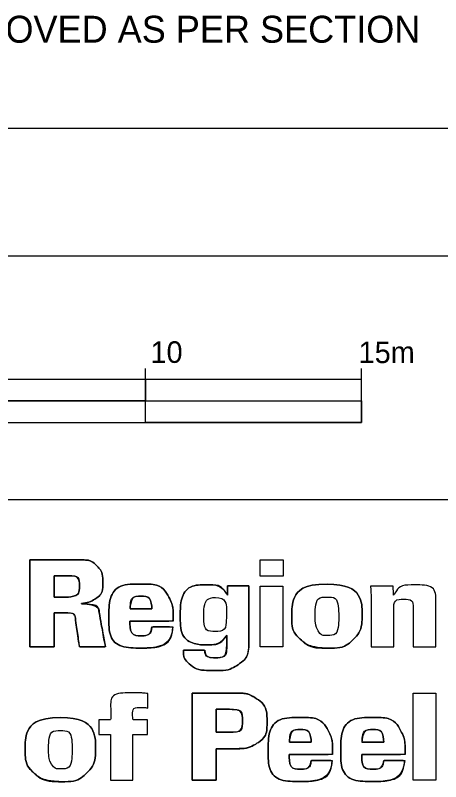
# Model space of a CAD drawing. Extents: x 612883 to 613093, y 4825734 to 4825879.
# Drawn here: x 613071.55 to 613081.4, y 4825752.4 to 4825770.16 of the extents above; entities that cross this region are included whole.
import ezdxf

# ---------------------------------------------------------------- set-up
doc = ezdxf.new("R2010")
doc.units = 0
for name, color, linetype in [('G-ANNO-BAR', 7, 'Continuous'), ('G-ANNO-TEXT', 7, 'Continuous'), ('G-TTLB-LOGO', 7, 'Continuous'), ('G-TTLB-OTLN', 7, 'Continuous')]:
    doc.layers.add(name, color=color, linetype=linetype)

msp = doc.modelspace()

# ---------------------------------------------------------------- linework, layer by layer
at = {"layer": 'G-ANNO-BAR'}
for p, q in [((613074.564, 4825760.723), (613074.564, 4825761.973)), ((613079.564, 4825760.723), (613079.564, 4825761.973)), ((613059.564, 4825761.723), (613079.564, 4825761.723)), ((613059.564, 4825761.223), (613079.564, 4825761.223)), ((613059.564, 4825760.723), (613079.564, 4825760.723))]:
    msp.add_line(p, q, dxfattribs=at)
for points in [[(613069.564, 4825761.723), (613074.564, 4825761.723), (613074.564, 4825761.223), (613069.564, 4825761.223)], [(613074.564, 4825761.223), (613079.564, 4825761.223), (613079.564, 4825760.723), (613074.564, 4825760.723)]]:
    msp.add_lwpolyline(points, close=True, dxfattribs=at)
at = {"layer": 'G-TTLB-LOGO'}
for p, q in [((613077.215, 4825757.537), (613077.752, 4825757.537)), ((613077.215, 4825757.162), (613077.215, 4825757.537)), ((613077.752, 4825757.537), (613077.752, 4825757.162)), ((613077.752, 4825757.162), (613077.215, 4825757.162)), ((613077.22, 4825756.927), (613077.746, 4825756.927)), ((613077.22, 4825755.523), (613077.22, 4825756.927)), ((613077.746, 4825756.927), (613077.746, 4825755.523)), ((613073.082, 4825756.527), (613073.082, 4825756.516)), ((613074.204, 4825756.404), (613074.71, 4825756.404)), ((613075.205, 4825756.119), (613074.198, 4825756.119)), ((613074.707, 4825755.982), (613075.197, 4825755.982)), ((613076.443, 4825755.61), (613076.443, 4825755.795)), ((613073.636, 4825755.523), (613073.029, 4825755.523)), ((613075.439, 4825755.448), (613075.934, 4825755.448)), ((613077.746, 4825755.523), (613077.22, 4825755.523)), ((613080.763, 4825754.449), (613081.289, 4825754.449)), ((613080.763, 4825752.43), (613080.763, 4825754.449)), ((613081.289, 4825754.449), (613081.289, 4825752.43)), ((613077.896, 4825753.311), (613078.402, 4825753.311)), ((613079.577, 4825753.311), (613080.083, 4825753.311)), ((613078.897, 4825753.025), (613077.89, 4825753.025)), ((613080.578, 4825753.025), (613079.571, 4825753.025)), ((613078.399, 4825752.888), (613078.888, 4825752.888)), ((613080.08, 4825752.888), (613080.569, 4825752.888)), ((613081.289, 4825752.43), (613080.763, 4825752.43))]:
    msp.add_line(p, q, dxfattribs=at)
for points in [[(613072.677, 4825756.312), (613072.442, 4825756.312), (613072.442, 4825755.523), (613071.88, 4825755.523), (613071.88, 4825757.542), (613072.814, 4825757.542)], [(613077.215, 4825757.537), (613077.752, 4825757.537), (613077.752, 4825757.162), (613077.215, 4825757.162), (613077.215, 4825757.537)], [(613072.652, 4825757.171), (613072.442, 4825757.171), (613072.442, 4825756.676), (613072.652, 4825756.676)], [(613076.46, 4825756.723), (613076.46, 4825756.936), (613076.955, 4825756.936), (613076.955, 4825755.627)], [(613077.22, 4825756.927), (613077.746, 4825756.927), (613077.746, 4825755.523), (613077.22, 4825755.523), (613077.22, 4825756.927)], [(613076.565, 4825753.16), (613076.201, 4825753.157), (613076.201, 4825752.43), (613075.639, 4825752.43), (613075.639, 4825754.449), (613076.567, 4825754.449)], [(613080.763, 4825754.449), (613081.289, 4825754.449), (613081.289, 4825752.43), (613080.763, 4825752.43), (613080.763, 4825754.449)], [(613076.447, 4825754.074), (613076.201, 4825754.074), (613076.201, 4825753.543), (613076.45, 4825753.543)]]:
    msp.add_lwpolyline(points, dxfattribs=at)
for points in [[(613071.88, 4825757.542), (613071.88, 4825757.542), (613072.814, 4825757.542), (613072.814, 4825757.542), (613073.177, 4825757.542), (613073.314, 4825757.52), (613073.435, 4825757.397), (613073.496, 4825757.336), (613073.574, 4825757.224), (613073.574, 4825757.006), (613073.574, 4825756.785), (613073.485, 4825756.69), (613073.39, 4825756.631), (613073.261, 4825756.55), (613073.138, 4825756.536), (613073.082, 4825756.527), (613073.082, 4825756.527), (613073.082, 4825756.516), (613073.082, 4825756.516), (613073.474, 4825756.505), (613073.482, 4825756.333), (613073.541, 4825756.021), (613073.567, 4825755.885), (613073.612, 4825755.621), (613073.636, 4825755.523), (613073.636, 4825755.523), (613073.029, 4825755.523), (613073.029, 4825755.523), (613073.019, 4825755.595), (613072.991, 4825755.805), (613072.967, 4825755.96), (613072.931, 4825756.202), (613072.928, 4825756.312), (613072.677, 4825756.312), (613072.677, 4825756.312), (613072.442, 4825756.312), (613072.442, 4825756.312), (613072.442, 4825756.312), (613072.442, 4825755.523), (613072.442, 4825755.523), (613072.442, 4825755.523), (613071.88, 4825755.523), (613071.88, 4825755.523), (613071.88, 4825755.523), (613071.88, 4825757.542), (613071.88, 4825757.542)], [(613072.814, 4825757.542), (613073.177, 4825757.542), (613073.314, 4825757.52), (613073.435, 4825757.397), (613073.496, 4825757.336), (613073.574, 4825757.224), (613073.574, 4825757.006), (613073.574, 4825756.785), (613073.485, 4825756.69), (613073.39, 4825756.631), (613073.261, 4825756.55), (613073.138, 4825756.536), (613073.082, 4825756.527)], [(613072.442, 4825756.676), (613072.442, 4825756.676), (613072.652, 4825756.676), (613072.652, 4825756.676), (613072.775, 4825756.676), (613072.836, 4825756.676), (613072.884, 4825756.692), (613073.007, 4825756.732), (613073.032, 4825756.857), (613073.032, 4825756.922), (613073.032, 4825757.171), (613072.814, 4825757.171), (613072.652, 4825757.171), (613072.652, 4825757.171), (613072.442, 4825757.171), (613072.442, 4825757.171), (613072.442, 4825757.171), (613072.442, 4825756.676), (613072.442, 4825756.676)], [(613072.652, 4825756.676), (613072.775, 4825756.676), (613072.836, 4825756.676), (613072.884, 4825756.692), (613073.007, 4825756.732), (613073.032, 4825756.857), (613073.032, 4825756.922), (613073.032, 4825757.171), (613072.814, 4825757.171), (613072.652, 4825757.171)], [(613074.198, 4825756.119), (613074.198, 4825756.044), (613074.198, 4825755.778), (613074.467, 4825755.778), (613074.607, 4825755.778), (613074.693, 4825755.851), (613074.707, 4825755.982), (613074.707, 4825755.982), (613075.197, 4825755.982), (613075.197, 4825755.982), (613075.158, 4825755.63), (613074.828, 4825755.493), (613074.464, 4825755.493), (613073.975, 4825755.493), (613073.712, 4825755.739), (613073.712, 4825756.203), (613073.712, 4825756.673), (613073.941, 4825756.978), (613074.458, 4825756.978), (613074.85, 4825756.978), (613075.032, 4825756.818), (613075.127, 4825756.62), (613075.188, 4825756.499), (613075.205, 4825756.365), (613075.205, 4825756.119), (613075.205, 4825756.119), (613074.198, 4825756.119), (613074.198, 4825756.119)], [(613075.197, 4825755.982), (613075.158, 4825755.63), (613074.828, 4825755.493), (613074.464, 4825755.493), (613073.975, 4825755.493), (613073.712, 4825755.739), (613073.712, 4825756.203), (613073.712, 4825756.673), (613073.941, 4825756.978), (613074.458, 4825756.978), (613074.85, 4825756.978), (613075.032, 4825756.818), (613075.127, 4825756.62), (613075.188, 4825756.499), (613075.205, 4825756.365), (613075.205, 4825756.119)], [(613076.955, 4825756.936), (613076.955, 4825756.936), (613076.955, 4825755.627), (613076.955, 4825755.627), (613076.955, 4825755.459), (613076.921, 4825755.261), (613076.731, 4825755.126), (613076.611, 4825755.04), (613076.44, 4825754.97), (613076.153, 4825754.97), (613075.993, 4825754.97), (613075.727, 4825754.992), (613075.568, 4825755.135), (613075.445, 4825755.244), (613075.442, 4825755.375), (613075.439, 4825755.448), (613075.439, 4825755.448), (613075.934, 4825755.448), (613075.934, 4825755.448), (613075.937, 4825755.342), (613076.013, 4825755.269), (613076.164, 4825755.269), (613076.427, 4825755.269), (613076.443, 4825755.459), (613076.443, 4825755.61), (613076.443, 4825755.61), (613076.443, 4825755.795), (613076.443, 4825755.795), (613076.301, 4825755.582), (613076.071, 4825755.568), (613075.99, 4825755.568), (613075.694, 4825755.568), (613075.367, 4825755.753), (613075.367, 4825756.265), (613075.367, 4825756.645), (613075.568, 4825756.961), (613075.996, 4825756.961), (613076.267, 4825756.961), (613076.39, 4825756.835), (613076.46, 4825756.723), (613076.46, 4825756.723), (613076.46, 4825756.936), (613076.46, 4825756.936), (613076.46, 4825756.936), (613076.955, 4825756.936), (613076.955, 4825756.936)], [(613076.443, 4825755.795), (613076.301, 4825755.582), (613076.071, 4825755.568), (613075.99, 4825755.568), (613075.694, 4825755.568), (613075.367, 4825755.753), (613075.367, 4825756.265), (613075.367, 4825756.645), (613075.568, 4825756.961), (613075.996, 4825756.961), (613076.267, 4825756.961), (613076.39, 4825756.835), (613076.46, 4825756.723)], [(613078.77, 4825756.975), (613079.226, 4825756.975), (613079.581, 4825756.746), (613079.581, 4825756.248), (613079.581, 4825756.044), (613079.522, 4825755.837), (613079.377, 4825755.691), (613079.259, 4825755.577), (613079.086, 4825755.49), (613078.798, 4825755.49), (613078.487, 4825755.49), (613078.286, 4825755.565), (613078.149, 4825755.697), (613077.987, 4825755.851), (613077.948, 4825756.06), (613077.948, 4825756.231), (613077.948, 4825756.662), (613078.213, 4825756.975), (613078.77, 4825756.975)], [(613078.62, 4825755.499), (613078.407, 4825755.523), (613078.258, 4825755.592), (613078.149, 4825755.697), (613077.987, 4825755.851), (613077.948, 4825756.06), (613077.948, 4825756.231), (613077.948, 4825756.662), (613078.213, 4825756.975), (613078.77, 4825756.975)], [(613078.77, 4825756.975), (613079.226, 4825756.975), (613079.581, 4825756.746), (613079.581, 4825756.248), (613079.581, 4825756.044), (613079.522, 4825755.837), (613079.377, 4825755.691), (613079.259, 4825755.577), (613079.086, 4825755.49), (613078.798, 4825755.49), (613078.734, 4825755.49), (613078.675, 4825755.493), (613078.62, 4825755.499)], [(613079.79, 4825756.628), (613079.79, 4825756.628), (613079.776, 4825756.927), (613079.776, 4825756.927), (613079.776, 4825756.927), (613080.301, 4825756.927), (613080.301, 4825756.927), (613080.301, 4825756.927), (613080.307, 4825756.712), (613080.307, 4825756.712), (613080.371, 4825756.818), (613080.483, 4825756.958), (613080.774, 4825756.958), (613081.289, 4825756.958), (613081.289, 4825756.567), (613081.289, 4825756.374), (613081.289, 4825756.374), (613081.289, 4825755.523), (613081.289, 4825755.523), (613081.289, 4825755.523), (613080.763, 4825755.523), (613080.763, 4825755.523), (613080.763, 4825755.523), (613080.763, 4825756.329), (613080.763, 4825756.329), (613080.763, 4825756.427), (613080.763, 4825756.625), (613080.548, 4825756.625), (613080.313, 4825756.625), (613080.313, 4825756.379), (613080.313, 4825756.329), (613080.313, 4825756.329), (613080.313, 4825755.523), (613080.313, 4825755.523), (613080.313, 4825755.523), (613079.79, 4825755.523), (613079.79, 4825755.523), (613079.79, 4825755.523), (613079.79, 4825756.628), (613079.79, 4825756.628)], [(613079.79, 4825756.628), (613079.79, 4825756.628), (613079.776, 4825756.927), (613079.776, 4825756.927), (613079.776, 4825756.927), (613080.301, 4825756.927), (613080.301, 4825756.927), (613080.301, 4825756.927), (613080.307, 4825756.712), (613080.307, 4825756.712), (613080.371, 4825756.818), (613080.483, 4825756.958), (613080.774, 4825756.958), (613081.289, 4825756.958), (613081.289, 4825756.567), (613081.289, 4825756.374), (613081.289, 4825756.374), (613081.289, 4825755.523), (613081.289, 4825755.523), (613081.289, 4825755.523), (613080.763, 4825755.523), (613080.763, 4825755.523), (613080.763, 4825755.523), (613080.763, 4825756.329), (613080.763, 4825756.329), (613080.763, 4825756.427), (613080.763, 4825756.625), (613080.548, 4825756.625), (613080.313, 4825756.625), (613080.313, 4825756.379), (613080.313, 4825756.329), (613080.313, 4825756.329), (613080.313, 4825755.523), (613080.313, 4825755.523), (613080.313, 4825755.523), (613079.79, 4825755.523), (613079.79, 4825755.523), (613079.79, 4825755.523), (613079.79, 4825756.628), (613079.79, 4825756.628)], [(613074.71, 4825756.404), (613074.705, 4825756.485), (613074.688, 4825756.698), (613074.458, 4825756.698), (613074.229, 4825756.698), (613074.21, 4825756.471), (613074.204, 4825756.404), (613074.204, 4825756.404), (613074.71, 4825756.404), (613074.71, 4825756.404)], [(613074.71, 4825756.404), (613074.705, 4825756.485), (613074.688, 4825756.698), (613074.458, 4825756.698), (613074.229, 4825756.698), (613074.21, 4825756.471), (613074.204, 4825756.404)], [(613076.18, 4825756.667), (613076.004, 4825756.667), (613075.909, 4825756.505), (613075.909, 4825756.27), (613075.909, 4825756.122), (613075.943, 4825755.879), (613076.175, 4825755.879), (613076.427, 4825755.879), (613076.435, 4825756.175), (613076.435, 4825756.276), (613076.435, 4825756.348), (613076.435, 4825756.667), (613076.18, 4825756.667)], [(613076.18, 4825756.667), (613076.004, 4825756.667), (613075.909, 4825756.505), (613075.909, 4825756.27), (613075.909, 4825756.122), (613075.943, 4825755.879), (613076.175, 4825755.879), (613076.427, 4825755.879), (613076.435, 4825756.175), (613076.435, 4825756.276), (613076.435, 4825756.348), (613076.435, 4825756.667), (613076.18, 4825756.667)], [(613078.56, 4825755.895), (613078.622, 4825755.789), (613078.717, 4825755.784), (613078.764, 4825755.784), (613078.994, 4825755.784), (613079.038, 4825756.032), (613079.038, 4825756.228), (613079.038, 4825756.471), (613078.98, 4825756.676), (613078.77, 4825756.676), (613078.538, 4825756.676), (613078.493, 4825756.438), (613078.493, 4825756.228), (613078.493, 4825756.136), (613078.501, 4825755.999), (613078.56, 4825755.895)], [(613078.56, 4825755.895), (613078.622, 4825755.789), (613078.717, 4825755.784), (613078.764, 4825755.784), (613078.994, 4825755.784), (613079.038, 4825756.032), (613079.038, 4825756.228), (613079.038, 4825756.471), (613078.98, 4825756.676), (613078.77, 4825756.676), (613078.538, 4825756.676), (613078.493, 4825756.438), (613078.493, 4825756.228), (613078.493, 4825756.136), (613078.501, 4825755.999), (613078.56, 4825755.895)], [(613073.082, 4825756.516), (613073.474, 4825756.505), (613073.482, 4825756.333), (613073.541, 4825756.021), (613073.567, 4825755.885), (613073.612, 4825755.621), (613073.636, 4825755.523)], [(613073.029, 4825755.523), (613073.019, 4825755.595), (613072.991, 4825755.805), (613072.967, 4825755.96), (613072.931, 4825756.202), (613072.928, 4825756.312), (613072.677, 4825756.312)], [(613074.198, 4825756.119), (613074.198, 4825756.044), (613074.198, 4825755.778), (613074.467, 4825755.778), (613074.607, 4825755.778), (613074.693, 4825755.851), (613074.707, 4825755.982)], [(613076.955, 4825755.627), (613076.955, 4825755.459), (613076.921, 4825755.261), (613076.731, 4825755.126), (613076.611, 4825755.04), (613076.44, 4825754.97), (613076.153, 4825754.97), (613075.993, 4825754.97), (613075.727, 4825754.992), (613075.568, 4825755.135), (613075.445, 4825755.244), (613075.442, 4825755.375), (613075.439, 4825755.448)], [(613075.934, 4825755.448), (613075.937, 4825755.342), (613076.013, 4825755.269), (613076.164, 4825755.269), (613076.427, 4825755.269), (613076.443, 4825755.459), (613076.443, 4825755.61)], [(613074.618, 4825754.102), (613074.596, 4825754.108), (613074.543, 4825754.119), (613074.473, 4825754.119), (613074.257, 4825754.119), (613074.263, 4825753.945), (613074.266, 4825753.828), (613074.266, 4825753.828), (613074.604, 4825753.828), (613074.604, 4825753.828), (613074.604, 4825753.828), (613074.604, 4825753.487), (613074.604, 4825753.487), (613074.604, 4825753.487), (613074.266, 4825753.487), (613074.266, 4825753.487), (613074.266, 4825753.487), (613074.266, 4825752.43), (613074.266, 4825752.43), (613074.266, 4825752.43), (613073.751, 4825752.43), (613073.751, 4825752.43), (613073.751, 4825752.43), (613073.751, 4825753.487), (613073.751, 4825753.487), (613073.751, 4825753.487), (613073.48, 4825753.487), (613073.48, 4825753.487), (613073.48, 4825753.487), (613073.48, 4825753.828), (613073.48, 4825753.828), (613073.48, 4825753.828), (613073.76, 4825753.828), (613073.76, 4825753.828), (613073.751, 4825754.164), (613073.757, 4825754.457), (613074.308, 4825754.457), (613074.451, 4825754.457), (613074.559, 4825754.446), (613074.618, 4825754.44), (613074.618, 4825754.44), (613074.618, 4825754.102), (613074.618, 4825754.102)], [(613074.618, 4825754.102), (613074.596, 4825754.108), (613074.543, 4825754.119), (613074.473, 4825754.119), (613074.257, 4825754.119), (613074.263, 4825753.945), (613074.266, 4825753.828), (613074.266, 4825753.828), (613074.604, 4825753.828), (613074.604, 4825753.828), (613074.604, 4825753.828), (613074.604, 4825753.487), (613074.604, 4825753.487), (613074.604, 4825753.487), (613074.266, 4825753.487), (613074.266, 4825753.487), (613074.266, 4825753.487), (613074.266, 4825752.43), (613074.266, 4825752.43), (613074.266, 4825752.43), (613073.751, 4825752.43), (613073.751, 4825752.43), (613073.751, 4825752.43), (613073.751, 4825753.487), (613073.751, 4825753.487), (613073.751, 4825753.487), (613073.48, 4825753.487), (613073.48, 4825753.487), (613073.48, 4825753.487), (613073.48, 4825753.828), (613073.48, 4825753.828), (613073.48, 4825753.828), (613073.76, 4825753.828), (613073.76, 4825753.828), (613073.751, 4825754.164), (613073.757, 4825754.457), (613074.308, 4825754.457), (613074.451, 4825754.457), (613074.559, 4825754.446), (613074.618, 4825754.44), (613074.618, 4825754.44), (613074.618, 4825754.102), (613074.618, 4825754.102)], [(613075.639, 4825754.449), (613075.639, 4825754.449), (613076.567, 4825754.449), (613076.567, 4825754.449), (613076.724, 4825754.449), (613076.928, 4825754.449), (613077.093, 4825754.345), (613077.264, 4825754.242), (613077.378, 4825754.06), (613077.378, 4825753.797), (613077.378, 4825753.442), (613077.152, 4825753.288), (613077.074, 4825753.246), (613076.917, 4825753.16), (613076.674, 4825753.16), (613076.565, 4825753.16), (613076.565, 4825753.16), (613076.201, 4825753.157), (613076.201, 4825753.157), (613076.201, 4825753.157), (613076.201, 4825752.43), (613076.201, 4825752.43), (613076.201, 4825752.43), (613075.639, 4825752.43), (613075.639, 4825752.43), (613075.639, 4825752.43), (613075.639, 4825754.449), (613075.639, 4825754.449)], [(613076.567, 4825754.449), (613076.724, 4825754.449), (613076.928, 4825754.449), (613077.093, 4825754.345), (613077.264, 4825754.242), (613077.378, 4825754.06), (613077.378, 4825753.797), (613077.378, 4825753.442), (613077.152, 4825753.288), (613077.074, 4825753.246), (613076.917, 4825753.16), (613076.674, 4825753.16), (613076.565, 4825753.16)], [(613076.201, 4825753.543), (613076.201, 4825753.543), (613076.45, 4825753.543), (613076.45, 4825753.543), (613076.587, 4825753.543), (613076.808, 4825753.543), (613076.808, 4825753.814), (613076.808, 4825754.06), (613076.609, 4825754.074), (613076.447, 4825754.074), (613076.447, 4825754.074), (613076.201, 4825754.074), (613076.201, 4825754.074), (613076.201, 4825754.074), (613076.201, 4825753.543), (613076.201, 4825753.543)], [(613076.45, 4825753.543), (613076.587, 4825753.543), (613076.808, 4825753.543), (613076.808, 4825753.814), (613076.808, 4825754.06), (613076.609, 4825754.074), (613076.447, 4825754.074)], [(613072.593, 4825753.881), (613073.049, 4825753.881), (613073.404, 4825753.652), (613073.404, 4825753.154), (613073.404, 4825752.95), (613073.345, 4825752.743), (613073.2, 4825752.598), (613073.082, 4825752.483), (613072.909, 4825752.396), (613072.621, 4825752.396), (613072.31, 4825752.396), (613072.109, 4825752.472), (613071.972, 4825752.603), (613071.81, 4825752.757), (613071.771, 4825752.967), (613071.771, 4825753.137), (613071.771, 4825753.568), (613072.036, 4825753.881), (613072.593, 4825753.881)], [(613072.443, 4825752.406), (613072.23, 4825752.43), (613072.081, 4825752.499), (613071.972, 4825752.603), (613071.81, 4825752.757), (613071.771, 4825752.967), (613071.771, 4825753.137), (613071.771, 4825753.568), (613072.036, 4825753.881), (613072.593, 4825753.881)], [(613072.593, 4825753.881), (613073.049, 4825753.881), (613073.404, 4825753.652), (613073.404, 4825753.154), (613073.404, 4825752.95), (613073.345, 4825752.743), (613073.2, 4825752.598), (613073.082, 4825752.483), (613072.909, 4825752.396), (613072.621, 4825752.396), (613072.557, 4825752.396), (613072.498, 4825752.399), (613072.443, 4825752.406)], [(613077.89, 4825753.025), (613077.89, 4825752.95), (613077.89, 4825752.684), (613078.159, 4825752.684), (613078.298, 4825752.684), (613078.385, 4825752.757), (613078.399, 4825752.888), (613078.399, 4825752.888), (613078.888, 4825752.888), (613078.888, 4825752.888), (613078.849, 4825752.536), (613078.519, 4825752.399), (613078.156, 4825752.399), (613077.666, 4825752.399), (613077.404, 4825752.645), (613077.404, 4825753.109), (613077.404, 4825753.579), (613077.633, 4825753.884), (613078.15, 4825753.884), (613078.542, 4825753.884), (613078.724, 4825753.725), (613078.819, 4825753.526), (613078.88, 4825753.406), (613078.897, 4825753.271), (613078.897, 4825753.025), (613078.897, 4825753.025), (613077.89, 4825753.025), (613077.89, 4825753.025)], [(613078.888, 4825752.888), (613078.849, 4825752.536), (613078.519, 4825752.399), (613078.156, 4825752.399), (613077.666, 4825752.399), (613077.404, 4825752.645), (613077.404, 4825753.109), (613077.404, 4825753.579), (613077.633, 4825753.884), (613078.15, 4825753.884), (613078.542, 4825753.884), (613078.724, 4825753.725), (613078.819, 4825753.526), (613078.88, 4825753.406), (613078.897, 4825753.271), (613078.897, 4825753.025)], [(613079.571, 4825753.025), (613079.571, 4825752.95), (613079.571, 4825752.684), (613079.839, 4825752.684), (613079.979, 4825752.684), (613080.066, 4825752.757), (613080.08, 4825752.888), (613080.08, 4825752.888), (613080.569, 4825752.888), (613080.569, 4825752.888), (613080.53, 4825752.536), (613080.2, 4825752.399), (613079.836, 4825752.399), (613079.347, 4825752.399), (613079.084, 4825752.645), (613079.084, 4825753.109), (613079.084, 4825753.579), (613079.314, 4825753.884), (613079.831, 4825753.884), (613080.222, 4825753.884), (613080.404, 4825753.725), (613080.499, 4825753.526), (613080.561, 4825753.406), (613080.578, 4825753.271), (613080.578, 4825753.025), (613080.578, 4825753.025), (613079.571, 4825753.025), (613079.571, 4825753.025)], [(613080.569, 4825752.888), (613080.53, 4825752.536), (613080.2, 4825752.399), (613079.836, 4825752.399), (613079.347, 4825752.399), (613079.084, 4825752.645), (613079.084, 4825753.109), (613079.084, 4825753.579), (613079.314, 4825753.884), (613079.831, 4825753.884), (613080.222, 4825753.884), (613080.404, 4825753.725), (613080.499, 4825753.526), (613080.561, 4825753.406), (613080.578, 4825753.271), (613080.578, 4825753.025)], [(613072.383, 4825752.802), (613072.445, 4825752.695), (613072.54, 4825752.69), (613072.587, 4825752.69), (613072.817, 4825752.69), (613072.861, 4825752.939), (613072.861, 4825753.134), (613072.861, 4825753.378), (613072.803, 4825753.582), (613072.593, 4825753.582), (613072.361, 4825753.582), (613072.316, 4825753.344), (613072.316, 4825753.134), (613072.316, 4825753.042), (613072.324, 4825752.905), (613072.383, 4825752.802)], [(613072.383, 4825752.802), (613072.445, 4825752.695), (613072.54, 4825752.69), (613072.587, 4825752.69), (613072.817, 4825752.69), (613072.861, 4825752.939), (613072.861, 4825753.134), (613072.861, 4825753.378), (613072.803, 4825753.582), (613072.593, 4825753.582), (613072.361, 4825753.582), (613072.316, 4825753.344), (613072.316, 4825753.134), (613072.316, 4825753.042), (613072.324, 4825752.905), (613072.383, 4825752.802)], [(613078.402, 4825753.311), (613078.396, 4825753.392), (613078.38, 4825753.604), (613078.15, 4825753.604), (613077.921, 4825753.604), (613077.901, 4825753.378), (613077.896, 4825753.311), (613077.896, 4825753.311), (613078.402, 4825753.311), (613078.402, 4825753.311)], [(613078.402, 4825753.311), (613078.396, 4825753.392), (613078.38, 4825753.604), (613078.15, 4825753.604), (613077.921, 4825753.604), (613077.901, 4825753.378), (613077.896, 4825753.311)], [(613080.083, 4825753.311), (613080.077, 4825753.392), (613080.06, 4825753.604), (613079.831, 4825753.604), (613079.602, 4825753.604), (613079.582, 4825753.378), (613079.577, 4825753.311), (613079.577, 4825753.311), (613080.083, 4825753.311), (613080.083, 4825753.311)], [(613080.083, 4825753.311), (613080.077, 4825753.392), (613080.06, 4825753.604), (613079.831, 4825753.604), (613079.602, 4825753.604), (613079.582, 4825753.378), (613079.577, 4825753.311)], [(613077.89, 4825753.025), (613077.89, 4825752.95), (613077.89, 4825752.684), (613078.159, 4825752.684), (613078.298, 4825752.684), (613078.385, 4825752.757), (613078.399, 4825752.888)], [(613079.571, 4825753.025), (613079.571, 4825752.95), (613079.571, 4825752.684), (613079.839, 4825752.684), (613079.979, 4825752.684), (613080.066, 4825752.757), (613080.08, 4825752.888)]]:
    msp.add_open_spline(points, degree=3, dxfattribs=at)
at = {"layer": 'G-TTLB-OTLN'}
for p, q in [((613090.1, 4825767.538), (613058.399, 4825767.538)), ((612893.054, 4825764.585), (613090.1, 4825764.584)), ((613090.1, 4825758.926), (613058.399, 4825758.926))]:
    msp.add_line(p, q, dxfattribs=at)

# ---------------------------------------------------------------- texts
at = {"layer": 'G-ANNO-BAR'}
for s, p in [('10', (613074.677, 4825762.104)), ('15m', (613079.499, 4825762.099))]:
    msp.add_text(s, height=0.5, rotation=360, dxfattribs=at).set_placement(p)
at = {"layer": 'G-ANNO-TEXT'}
msp.add_text('SIGNAL INSTALLATION APPROVED AS PER SECTION', height=0.625, dxfattribs=at).set_placement((613059.565, 4825769.526))

doc.saveas('drawing.dxf')
